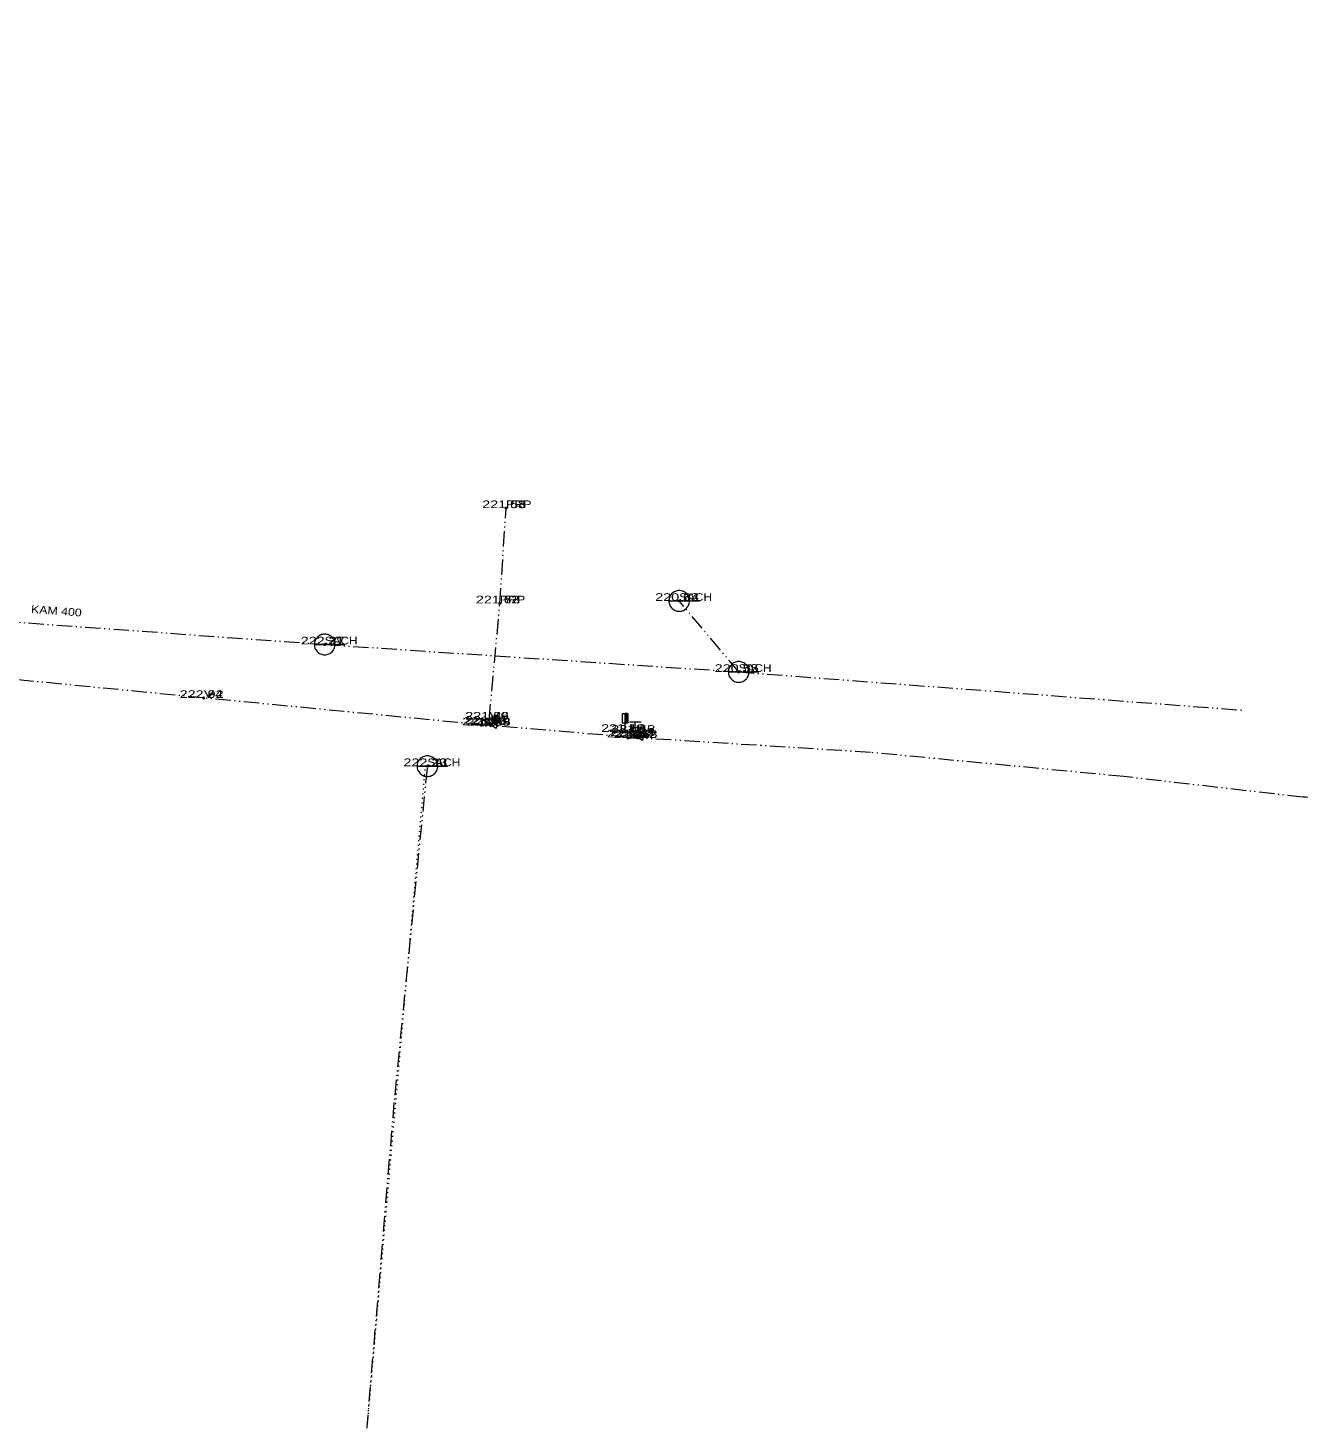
# Model space of a CAD drawing. Extents: x -662912 to -662645, y -1059528 to -1059126.
# Drawn here: x -662769.8 to -662644.9, y -1059528.5 to -1059391.8 of the extents above; entities that cross this region are included whole.
import ezdxf
from ezdxf.enums import TextEntityAlignment as Align

# ---------------------------------------------------------------- set-up
doc = ezdxf.new("R2010")
doc.units = 0
doc.header["$LTSCALE"] = 0.3
doc.header["$PDMODE"] = 32
doc.header["$PDSIZE"] = 0.15
doc.linetypes.add('DASH_DOUBLE_DOT', pattern=[9.2, 5, -1.2, 0.3, -1.2, 0.3, -1.2])
doc.linetypes.add('DOTTED', pattern=[1.5, 0.3, -1.2])
for name, color, linetype in [('1', 7, 'Continuous'), ('18', 7, 'Continuous'), ('2', 7, 'Continuous'), ('3', 7, 'Continuous'), ('63', 7, 'Continuous')]:
    doc.layers.add(name, color=color, linetype=linetype)
for name, color, linetype, lineweight in [('10', 7, 'Continuous', 13), ('12', 7, 'Continuous', 13), ('35', 7, 'DASH_DOUBLE_DOT', 13), ('46', 7, 'DOTTED', 13), ('50', 7, 'DASH_DOUBLE_DOT', 13), ('51', 7, 'DASH_DOUBLE_DOT', 13)]:
    doc.layers.add(name, color=color, linetype=linetype, lineweight=lineweight)

msp = doc.modelspace()

# ---------------------------------------------------------------- linework, layer by layer
at = {"layer": '1'}
for p in [(-662723.101, -1059438.7), (-662723.713, -1059447.994), (-662706.213, -1059447.752), (-662740.804, -1059452.004), (-662700.409, -1059454.683), (-662752.622, -1059457.222), (-662724.757, -1059459.338), (-662725.056, -1059459.884), (-662724.779, -1059459.746), (-662724.606, -1059459.92), (-662711.491, -1059460.538), (-662710.524, -1059460.95), (-662710.499, -1059460.631), (-662710.912, -1059461.068), (-662710.281, -1059461.119), (-662730.784, -1059463.881)]:
    msp.add_point(p, dxfattribs=at)
at = {"layer": '10'}
for p, q in [((-662711.393, -1059458.76), (-662711.491, -1059458.76)), ((-662711.491, -1059460.538), (-662711.491, -1059458.76)), ((-662711.344, -1059458.983), (-662711.344, -1059459.424)), ((-662711.058, -1059459.562), (-662709.94, -1059459.562)), ((-662710.104, -1059461.027), (-662710.894, -1059460.236)), ((-662710.499, -1059460.073), (-662710.499, -1059459.562))]:
    msp.add_line(p, q, dxfattribs=at)
for points in [[(-662723.986, -1059459.51), (-662724.088, -1059460.202), (-662725.47, -1059459.29), (-662725.572, -1059459.982)], [(-662711.792, -1059459.649), (-662711.19, -1059459.649), (-662711.19, -1059458.76), (-662711.792, -1059458.76)], [(-662711.414, -1059459.53), (-662711.267, -1059459.53), (-662711.267, -1059458.864), (-662711.414, -1059458.864)], [(-662709.744, -1059460.673), (-662709.811, -1059461.37), (-662711.237, -1059460.53), (-662711.304, -1059461.227)]]:
    msp.add_lwpolyline(points, close=True, dxfattribs=at)
for centre, radius in [((-662724.779, -1059459.746), 0.132), ((-662710.499, -1059460.632), 0.559), ((-662710.524, -1059460.95), 0.132)]:
    msp.add_circle(centre, radius, dxfattribs=at)
msp.add_point((-662711.393, -1059458.76), dxfattribs=at)
at = {"layer": '12'}
for p, q in [((-662707.221, -1059447.752), (-662704.244, -1059447.752)), ((-662741.812, -1059452.004), (-662738.835, -1059452.004)), ((-662701.417, -1059454.683), (-662698.44, -1059454.683)), ((-662731.792, -1059463.881), (-662728.815, -1059463.881))]:
    msp.add_line(p, q, dxfattribs=at)
for points in [[(-662706.213, -1059446.744), (-662706.318, -1059446.75), (-662706.422, -1059446.766), (-662706.524, -1059446.793), (-662706.622, -1059446.831), (-662706.716, -1059446.879), (-662706.804, -1059446.936), (-662706.887, -1059447.003), (-662706.962, -1059447.078), (-662707.028, -1059447.16), (-662707.085, -1059447.247), (-662707.132, -1059447.342), (-662707.17, -1059447.441), (-662707.198, -1059447.542), (-662707.214, -1059447.647), (-662707.221, -1059447.752), (-662707.214, -1059447.857), (-662707.198, -1059447.962), (-662707.17, -1059448.064), (-662707.132, -1059448.162), (-662707.085, -1059448.255), (-662707.028, -1059448.345), (-662706.962, -1059448.427), (-662706.887, -1059448.501), (-662706.804, -1059448.567), (-662706.716, -1059448.625), (-662706.622, -1059448.673), (-662706.524, -1059448.711), (-662706.422, -1059448.738), (-662706.318, -1059448.754), (-662706.213, -1059448.76), (-662706.107, -1059448.754), (-662706.002, -1059448.738), (-662705.901, -1059448.711), (-662705.803, -1059448.673), (-662705.708, -1059448.625), (-662705.62, -1059448.567), (-662705.538, -1059448.501), (-662705.463, -1059448.427), (-662705.397, -1059448.345), (-662705.34, -1059448.255), (-662705.291, -1059448.162), (-662705.253, -1059448.064), (-662705.227, -1059447.962), (-662705.211, -1059447.857), (-662705.205, -1059447.752), (-662705.211, -1059447.647), (-662705.227, -1059447.542), (-662705.253, -1059447.441), (-662705.291, -1059447.342), (-662705.34, -1059447.247), (-662705.397, -1059447.16), (-662705.463, -1059447.078), (-662705.538, -1059447.003), (-662705.62, -1059446.936), (-662705.708, -1059446.879), (-662705.803, -1059446.831), (-662705.901, -1059446.793), (-662706.002, -1059446.766), (-662706.107, -1059446.75)], [(-662740.804, -1059450.996), (-662740.909, -1059451.002), (-662741.013, -1059451.018), (-662741.115, -1059451.045), (-662741.213, -1059451.083), (-662741.307, -1059451.131), (-662741.395, -1059451.188), (-662741.478, -1059451.255), (-662741.553, -1059451.33), (-662741.619, -1059451.412), (-662741.676, -1059451.499), (-662741.723, -1059451.594), (-662741.761, -1059451.693), (-662741.789, -1059451.794), (-662741.805, -1059451.899), (-662741.812, -1059452.004), (-662741.805, -1059452.109), (-662741.789, -1059452.214), (-662741.761, -1059452.316), (-662741.723, -1059452.414), (-662741.676, -1059452.507), (-662741.619, -1059452.597), (-662741.553, -1059452.679), (-662741.478, -1059452.753), (-662741.395, -1059452.819), (-662741.307, -1059452.877), (-662741.213, -1059452.925), (-662741.115, -1059452.963), (-662741.013, -1059452.99), (-662740.909, -1059453.006), (-662740.804, -1059453.012), (-662740.698, -1059453.006), (-662740.593, -1059452.99), (-662740.492, -1059452.963), (-662740.394, -1059452.925), (-662740.299, -1059452.877), (-662740.211, -1059452.819), (-662740.129, -1059452.753), (-662740.054, -1059452.679), (-662739.988, -1059452.597), (-662739.931, -1059452.507), (-662739.882, -1059452.414), (-662739.844, -1059452.316), (-662739.818, -1059452.214), (-662739.802, -1059452.109), (-662739.796, -1059452.004), (-662739.802, -1059451.899), (-662739.818, -1059451.794), (-662739.844, -1059451.693), (-662739.882, -1059451.594), (-662739.931, -1059451.499), (-662739.988, -1059451.412), (-662740.054, -1059451.33), (-662740.129, -1059451.255), (-662740.211, -1059451.188), (-662740.299, -1059451.131), (-662740.394, -1059451.083), (-662740.492, -1059451.045), (-662740.593, -1059451.018), (-662740.698, -1059451.002)], [(-662700.409, -1059453.675), (-662700.514, -1059453.681), (-662700.618, -1059453.697), (-662700.72, -1059453.724), (-662700.818, -1059453.762), (-662700.912, -1059453.81), (-662701, -1059453.867), (-662701.083, -1059453.934), (-662701.158, -1059454.009), (-662701.224, -1059454.091), (-662701.281, -1059454.178), (-662701.328, -1059454.273), (-662701.366, -1059454.372), (-662701.394, -1059454.473), (-662701.41, -1059454.578), (-662701.417, -1059454.683), (-662701.41, -1059454.788), (-662701.394, -1059454.893), (-662701.366, -1059454.995), (-662701.328, -1059455.093), (-662701.281, -1059455.186), (-662701.224, -1059455.276), (-662701.158, -1059455.358), (-662701.083, -1059455.432), (-662701, -1059455.498), (-662700.912, -1059455.556), (-662700.818, -1059455.604), (-662700.72, -1059455.642), (-662700.618, -1059455.669), (-662700.514, -1059455.685), (-662700.409, -1059455.691), (-662700.303, -1059455.685), (-662700.198, -1059455.669), (-662700.097, -1059455.642), (-662699.999, -1059455.604), (-662699.904, -1059455.556), (-662699.816, -1059455.498), (-662699.734, -1059455.432), (-662699.659, -1059455.358), (-662699.593, -1059455.276), (-662699.536, -1059455.186), (-662699.487, -1059455.093), (-662699.449, -1059454.995), (-662699.423, -1059454.893), (-662699.407, -1059454.788), (-662699.401, -1059454.683), (-662699.407, -1059454.578), (-662699.423, -1059454.473), (-662699.449, -1059454.372), (-662699.487, -1059454.273), (-662699.536, -1059454.178), (-662699.593, -1059454.091), (-662699.659, -1059454.009), (-662699.734, -1059453.934), (-662699.816, -1059453.867), (-662699.904, -1059453.81), (-662699.999, -1059453.762), (-662700.097, -1059453.724), (-662700.198, -1059453.697), (-662700.303, -1059453.681)], [(-662730.784, -1059462.873), (-662730.889, -1059462.879), (-662730.993, -1059462.895), (-662731.095, -1059462.922), (-662731.193, -1059462.96), (-662731.287, -1059463.008), (-662731.375, -1059463.065), (-662731.458, -1059463.132), (-662731.533, -1059463.207), (-662731.599, -1059463.289), (-662731.656, -1059463.376), (-662731.703, -1059463.471), (-662731.741, -1059463.57), (-662731.769, -1059463.671), (-662731.785, -1059463.776), (-662731.792, -1059463.881), (-662731.785, -1059463.986), (-662731.769, -1059464.091), (-662731.741, -1059464.193), (-662731.703, -1059464.291), (-662731.656, -1059464.384), (-662731.599, -1059464.474), (-662731.533, -1059464.556), (-662731.458, -1059464.63), (-662731.375, -1059464.696), (-662731.287, -1059464.754), (-662731.193, -1059464.802), (-662731.095, -1059464.84), (-662730.993, -1059464.867), (-662730.889, -1059464.883), (-662730.784, -1059464.889), (-662730.678, -1059464.883), (-662730.573, -1059464.867), (-662730.472, -1059464.84), (-662730.374, -1059464.802), (-662730.279, -1059464.754), (-662730.191, -1059464.696), (-662730.109, -1059464.63), (-662730.034, -1059464.556), (-662729.968, -1059464.474), (-662729.911, -1059464.384), (-662729.862, -1059464.291), (-662729.824, -1059464.193), (-662729.798, -1059464.091), (-662729.782, -1059463.986), (-662729.776, -1059463.881), (-662729.782, -1059463.776), (-662729.798, -1059463.671), (-662729.824, -1059463.57), (-662729.862, -1059463.471), (-662729.911, -1059463.376), (-662729.968, -1059463.289), (-662730.034, -1059463.207), (-662730.109, -1059463.132), (-662730.191, -1059463.065), (-662730.279, -1059463.008), (-662730.374, -1059462.96), (-662730.472, -1059462.922), (-662730.573, -1059462.895), (-662730.678, -1059462.879)]]:
    msp.add_lwpolyline(points, close=True, dxfattribs=at)
at = {"layer": '35'}
msp.add_lwpolyline([(-662644.859, -1059466.95), (-662645.112, -1059466.917), (-662645.372, -1059466.909), (-662662.83, -1059464.894), (-662687.561, -1059462.539), (-662710.281, -1059461.119), (-662710.912, -1059461.068), (-662724.606, -1059459.92), (-662725.056, -1059459.884), (-662752.622, -1059457.222), (-662778.784, -1059454.67), (-662779.314, -1059454.649), (-662794.161, -1059453.294), (-662835.989, -1059449.969), (-662853.804, -1059448.267), (-662862.662, -1059447.464), (-662863.016, -1059447.295), (-662862.989, -1059446.882), (-662862.778, -1059444.512), (-662862.395, -1059439.303), (-662859.734, -1059407.478), (-662859.299, -1059392.261), (-662859.11, -1059391.841)], dxfattribs=at)
at = {"layer": '46'}
msp.add_line((-662736.66, -1059528.47), (-662730.988, -1059463.975), dxfattribs=at)
at = {"layer": '46', "linetype": 'DASH_DOUBLE_DOT'}
for points in [[(-662825.236, -1059445.321), (-662783.579, -1059448.898), (-662740.804, -1059452.004), (-662700.409, -1059454.683), (-662651.258, -1059458.409)], [(-662730.82, -1059464.06), (-662734.044, -1059496.701), (-662736.695, -1059528.384)]]:
    msp.add_lwpolyline(points, dxfattribs=at)
at = {"layer": '50'}
msp.add_lwpolyline([(-662724.788, -1059459.905), (-662724.757, -1059459.338), (-662723.713, -1059447.994), (-662723.101, -1059438.7)], dxfattribs=at)
at = {"layer": '51'}
msp.add_line((-662700.409, -1059454.683), (-662706.213, -1059447.752), dxfattribs=at)

# ---------------------------------------------------------------- texts
at = {"layer": '18', "width": 1.2}
msp.add_text('KAM 400', height=0.75, rotation=355.847, dxfattribs=at).set_placement((-662769.479, -1059448.919))
at = {"layer": '2', "width": 1.35}
for s, p in [(' 63', (-662723.101, -1059438.7)), (' 33', (-662706.213, -1059447.752)), (' 62', (-662723.713, -1059447.994)), (' 31', (-662740.804, -1059452.004)), (' 32', (-662700.409, -1059454.683)), (' 64', (-662752.622, -1059457.222)), (' 57', (-662725.056, -1059459.884)), (' 61', (-662724.779, -1059459.746)), (' 60', (-662724.757, -1059459.338)), (' 59', (-662724.606, -1059459.92)), (' 56', (-662711.491, -1059460.538)), (' 53', (-662710.912, -1059461.068)), (' 54', (-662710.524, -1059460.95)), (' 55', (-662710.499, -1059460.631)), (' 52', (-662710.281, -1059461.119)), (' 20', (-662730.784, -1059463.881))]:
    msp.add_text(s, height=0.75, dxfattribs=at).set_placement(p)
at = {"layer": '3', "width": 1.4}
for s, p in [('221 58 ', (-662723.101, -1059438.7)), ('220 64 ', (-662706.213, -1059447.752)), ('221 73 ', (-662723.713, -1059447.994)), ('222 27 ', (-662740.804, -1059452.004)), ('220 55 ', (-662700.409, -1059454.683)), ('222 92 ', (-662752.622, -1059457.222)), ('221 90 ', (-662725.056, -1059459.884)), ('221 97 ', (-662724.779, -1059459.746)), ('221 86 ', (-662724.757, -1059459.338)), ('221 88 ', (-662724.606, -1059459.92)), ('221 15 ', (-662711.491, -1059460.538)), ('221 17 ', (-662710.912, -1059461.068)), ('221 12 ', (-662710.524, -1059460.95)), ('221 12 ', (-662710.499, -1059460.631)), ('221 13 ', (-662710.281, -1059461.119)), ('222 23 ', (-662730.784, -1059463.881))]:
    msp.add_text(s, height=0.75, dxfattribs=at).set_placement(p, align=Align.CENTER)
at = {"layer": '63'}
for s, width, p in [('PRP', 1.2, (-662723.101, -1059438.7)), ('SACH', 1.15, (-662706.213, -1059447.752)), ('PRP', 1.2, (-662723.713, -1059447.994)), ('SACH', 1.15, (-662740.804, -1059452.004)), ('SACH', 1.15, (-662700.409, -1059454.683)), ('V', 1.55, (-662752.622, -1059457.222)), ('V', 1.55, (-662725.056, -1059459.884)), ('V', 1.55, (-662724.757, -1059459.338)), ('S', 1.55, (-662724.779, -1059459.746)), ('V', 1.55, (-662724.606, -1059459.92)), ('V', 1.55, (-662710.912, -1059461.068)), ('S', 1.55, (-662710.524, -1059460.95)), ('H', 1.5, (-662710.499, -1059460.631)), ('V', 1.55, (-662710.281, -1059461.119)), ('SACH', 1.15, (-662730.784, -1059463.881))]:
    msp.add_text(s, height=0.75, dxfattribs=dict(at, width=width)).set_placement(p)

doc.saveas('drawing.dxf')
